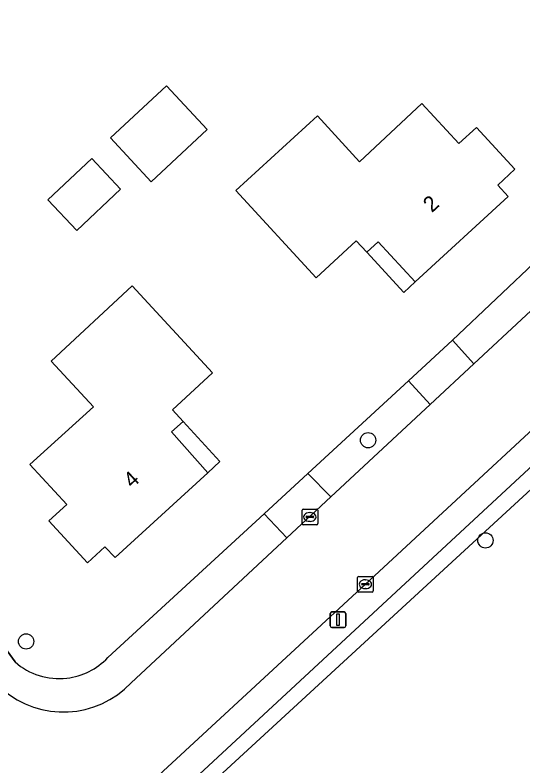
# Model space of a CAD drawing. Extents: x 162661 to 163484, y 380247 to 381230.
# Drawn here: x 163326.21 to 163358.76, y 380933.79 to 380981.87 of the extents above; entities that cross this region are included whole.
import ezdxf

# ---------------------------------------------------------------- set-up
doc = ezdxf.new("R2010")
doc.units = 0
for name, color, linetype in [('IMGEO_Berm_groen', 7, 'Continuous'), ('IMGEO_Boom', 7, 'Continuous'), ('IMGEO_Erf', 7, 'Continuous'), ('IMGEO_Groenvoorziening', 7, 'Continuous'), ('IMGEO_Kolk', 7, 'Continuous'), ('IMGEO_Lichtmast', 7, 'Continuous'), ('IMGEO_Pand', 7, 'Continuous'), ('IMGEO_Pand_nummerreeks', 7, 'Continuous'), ('IMGEO_Pand_overbouw', 7, 'Continuous'), ('IMGEO_Parkeervlak_halfverhard', 7, 'Continuous'), ('IMGEO_Rijbaan_lokaal_gesloten', 7, 'Continuous'), ('IMGEO_Voetpad_open', 7, 'Continuous')]:
    doc.layers.add(name, color=color, linetype=linetype)

msp = doc.modelspace()

# ---------------------------------------------------------------- linework, layer by layer
at = {"layer": 'IMGEO_Berm_groen'}
for points in [[(163326.207, 380940.39), (163325.261, 380941.733), (163311.978, 380956.021)], [(163333.656, 380939.059), (163343.629, 380948.342), (163342.164, 380949.894), (163332.151, 380940.668)]]:
    msp.add_lwpolyline(points, dxfattribs=at)
for centre, radius, start, end in [((163329.039, 380943.604), 4.278, 276.5116, 316.6709), ((163329.034, 380943.61), 4.285, 228.7142, 276.564), ((163329.301, 380943.161), 5.982, 229.0839, 316.7149)]:
    msp.add_arc(centre, radius, start, end, dxfattribs=at)
at = {"layer": 'IMGEO_Boom'}
for centre in [(163348.834, 380954.604), (163356.355, 380948.185), (163326.916, 380941.706)]:
    msp.add_circle(centre, 0.489, dxfattribs=at)
at = {"layer": 'IMGEO_Erf'}
for points in [[(163293.805, 380993.494), (163295.938, 380991.199), (163298.071, 380988.903), (163300.205, 380986.608), (163302.338, 380984.312), (163304.471, 380982.017), (163308.511, 380977.571), (163310.649, 380975.27), (163312.787, 380972.969), (163314.926, 380970.668), (163317.064, 380968.367), (163319.202, 380966.066), (163314.601, 380961.79), (163310.321, 380957.793), (163311.978, 380956.021), (163325.261, 380941.733), (163326.207, 380940.39)], [(163332.151, 380940.668), (163342.164, 380949.894), (163344.981, 380952.467), (163351.42, 380958.415), (163354.236, 380961.019), (163365.428, 380971.625)], [(163404.993, 380933.536), (163403.462, 380935.161), (163390.657, 380948.856), (163386.451, 380953.455), (163376.71, 380963.784), (163373.198, 380964.214), (163372.923, 380964.017), (163339.792, 380933.51), (163323.416, 380918.477), (163320.591, 380915.883), (163309.478, 380905.68), (163306.653, 380903.087), (163296.844, 380894.082)]]:
    msp.add_lwpolyline(points, dxfattribs=at)
for points in [[(163332.317, 380973.987), (163335.909, 380977.334), (163338.528, 380974.523), (163334.936, 380971.177)], [(163340.364, 380970.606), (163345.585, 380975.401), (163348.291, 380972.455), (163352.276, 380976.199), (163354.643, 380973.622), (163355.777, 380974.664), (163358.247, 380971.975), (163357.142, 380970.961), (163357.812, 380970.232), (163351.855, 380964.751), (163349.487, 380967.33), (163348.755, 380966.652), (163348.076, 380967.385), (163345.497, 380965.016)], [(163328.314, 380970.022), (163331.126, 380972.668), (163332.971, 380970.706), (163330.16, 380968.06)], [(163329.52, 380950.478), (163327.148, 380953.052), (163331.23, 380956.744), (163328.515, 380959.683), (163333.723, 380964.494), (163338.874, 380958.919), (163336.297, 380956.547), (163336.973, 380955.812), (163336.236, 380955.134), (163338.555, 380952.513), (163332.63, 380947.079), (163331.958, 380947.767), (163330.855, 380946.75), (163328.385, 380949.431)]]:
    msp.add_lwpolyline(points, close=True, dxfattribs=at)
for centre, radius, start, end in [((163329.039, 380943.604), 4.278, 276.5116, 316.6709), ((163329.034, 380943.61), 4.285, 228.7142, 276.564)]:
    msp.add_arc(centre, radius, start, end, dxfattribs=at)
at = {"layer": 'IMGEO_Groenvoorziening'}
for points in [[(163365.428, 380971.625), (163354.236, 380961.019), (163355.608, 380959.493), (163369.035, 380971.991), (163369.571, 380972.49), (163369.923, 380972.818), (163362.25, 380981.158), (163361.771, 380980.64), (163361.846, 380980.56), (163365.684, 380976.459)], [(163378.593, 380962.733), (163378.306, 380963.06), (163378.763, 380963.459), (163374.975, 380967.47), (163374.087, 380966.646), (163329.24, 380925.031), (163328.116, 380923.988), (163322.814, 380919.162), (163323.416, 380918.477), (163339.792, 380933.51), (163372.923, 380964.017), (163373.198, 380964.214), (163376.71, 380963.784), (163386.451, 380953.455), (163390.657, 380948.856), (163403.462, 380935.161), (163404.993, 380933.536)]]:
    msp.add_lwpolyline(points, dxfattribs=at)
msp.add_lwpolyline([(163346.451, 380950.969), (163352.811, 380956.889), (163351.42, 380958.415), (163344.981, 380952.467)], close=True, dxfattribs=at)
at = {"layer": 'IMGEO_Kolk'}
for p, q in [((163344.603, 380949.26), (163344.603, 380950.112)), ((163344.678, 380950.186), (163345.53, 380950.186)), ((163345.604, 380950.112), (163345.604, 380949.26)), ((163344.862, 380949.68), (163344.862, 380949.692)), ((163345.3, 380949.643), (163344.902, 380949.643)), ((163344.905, 380949.729), (163345.303, 380949.729)), ((163345.091, 380949.966), (163345.116, 380949.966)), ((163345.346, 380949.692), (163345.346, 380949.68)), ((163345.53, 380949.186), (163344.678, 380949.186)), ((163345.114, 380949.406), (163345.089, 380949.406)), ((163348.161, 380944.949), (163348.161, 380945.801)), ((163348.236, 380945.875), (163349.088, 380945.875)), ((163349.162, 380945.801), (163349.162, 380944.949)), ((163348.42, 380945.369), (163348.42, 380945.381)), ((163348.858, 380945.332), (163348.46, 380945.332)), ((163348.463, 380945.418), (163348.861, 380945.418)), ((163348.649, 380945.655), (163348.674, 380945.655)), ((163348.904, 380945.381), (163348.904, 380945.369)), ((163349.088, 380944.875), (163348.236, 380944.875)), ((163348.672, 380945.095), (163348.647, 380945.095))]:
    msp.add_line(p, q, dxfattribs=at)
for points in [[(163344.603, 380949.26), (163344.603, 380950.112)], [(163344.678, 380950.186), (163345.53, 380950.186)], [(163345.604, 380950.112), (163345.604, 380949.26)], [(163345.53, 380949.186), (163344.678, 380949.186)], [(163348.161, 380944.949), (163348.161, 380945.801)], [(163348.236, 380945.875), (163349.088, 380945.875)], [(163349.162, 380945.801), (163349.162, 380944.949)], [(163349.088, 380944.875), (163348.236, 380944.875)]]:
    msp.add_lwpolyline(points, dxfattribs=at)
for centre, radius, start, end in [((163344.68, 380950.11), 0.0765, 91.552, 178.448), ((163344.68, 380950.11), 0.0765, 91.552, 178.448), ((163345.528, 380950.11), 0.0765, 1.552, 88.448), ((163345.528, 380950.11), 0.0765, 1.552, 88.448), ((163344.902, 380949.689), 0.0403, 85.8775, 175.7526), ((163344.899, 380949.679), 0.0366, 178.938, 274.7102), ((163345.303, 380949.686), 0.043, 264.8664, 352.4533), ((163345.307, 380949.691), 0.0386, 1.7309, 96.639), ((163344.68, 380949.262), 0.0765, 181.552, 268.448), ((163344.68, 380949.262), 0.0765, 181.552, 268.448), ((163345.528, 380949.262), 0.0765, 271.552, 358.448), ((163345.528, 380949.262), 0.0765, 271.552, 358.448), ((163348.238, 380945.799), 0.0765, 91.552, 178.448), ((163348.238, 380945.799), 0.0765, 91.552, 178.448), ((163349.086, 380945.799), 0.0765, 1.552, 88.448), ((163349.086, 380945.799), 0.0765, 1.552, 88.448), ((163348.46, 380945.378), 0.0403, 85.8775, 175.7526), ((163348.457, 380945.368), 0.0366, 178.938, 274.7102), ((163348.861, 380945.375), 0.043, 264.8664, 352.4533), ((163348.865, 380945.38), 0.0386, 1.7309, 96.639), ((163348.238, 380944.951), 0.0765, 181.552, 268.448), ((163348.238, 380944.951), 0.0765, 181.552, 268.448), ((163349.086, 380944.951), 0.0765, 271.552, 358.448), ((163349.086, 380944.951), 0.0765, 271.552, 358.448)]:
    msp.add_arc(centre, radius, start, end, dxfattribs=at)
for centre, major_axis, ratio, start_param, end_param in [((163345.09, 380949.686), (-0.387, 0.002), 0.722429, 4.712389, 7.853982), ((163345.115, 380949.686), (-0.39, 0.002), 0.717154, 1.570796, 4.712389), ((163348.648, 380945.375), (-0.387, 0.002), 0.722429, 4.712389, 7.853982), ((163348.673, 380945.375), (-0.39, 0.002), 0.717154, 1.570796, 4.712389)]:
    msp.add_ellipse(centre, major_axis=major_axis, ratio=ratio, start_param=start_param, end_param=end_param, dxfattribs=at)
at = {"layer": 'IMGEO_Lichtmast'}
for p, q in [((163346.408, 380942.7), (163346.408, 380943.5)), ((163346.408, 380943.5), (163346.408, 380942.7)), ((163346.508, 380943.6), (163347.298, 380943.6)), ((163347.298, 380943.6), (163346.508, 380943.6)), ((163347.398, 380943.5), (163347.398, 380942.7)), ((163347.398, 380942.7), (163347.398, 380943.5)), ((163347.298, 380942.6), (163346.508, 380942.6)), ((163346.508, 380942.6), (163347.298, 380942.6))]:
    msp.add_line(p, q, dxfattribs=at)
msp.add_lwpolyline([(163346.828, 380943.475), (163346.978, 380943.475), (163346.978, 380942.725), (163346.828, 380942.725), (163346.828, 380943.475)], dxfattribs=at)
for centre, start, end in [((163346.508, 380943.5), 90, 180), ((163346.508, 380943.5), 90, 180), ((163347.298, 380943.5), 0, 90), ((163347.298, 380943.5), 360, 90), ((163346.508, 380942.7), 180, 270), ((163346.508, 380942.7), 180, 270), ((163347.298, 380942.7), 270, 0), ((163347.298, 380942.7), 270, 0)]:
    msp.add_arc(centre, 0.1, start, end, dxfattribs=at)
at = {"layer": 'IMGEO_Pand'}
for points in [[(163332.317, 380973.987), (163334.936, 380971.177), (163338.528, 380974.523), (163335.909, 380977.334)], [(163348.755, 380966.652), (163349.487, 380967.33), (163351.855, 380964.751), (163357.812, 380970.232), (163357.142, 380970.961), (163358.247, 380971.975), (163355.777, 380974.664), (163354.643, 380973.622), (163352.276, 380976.199), (163348.291, 380972.455), (163345.585, 380975.401), (163340.364, 380970.606), (163345.497, 380965.016), (163348.076, 380967.385)], [(163328.314, 380970.022), (163330.16, 380968.06), (163332.971, 380970.706), (163331.126, 380972.668)], [(163338.555, 380952.513), (163336.236, 380955.134), (163336.973, 380955.812), (163336.297, 380956.547), (163338.874, 380958.919), (163333.723, 380964.494), (163328.515, 380959.683), (163331.23, 380956.744), (163327.148, 380953.052), (163329.52, 380950.478), (163328.385, 380949.431), (163330.855, 380946.75), (163331.958, 380947.767), (163332.63, 380947.079)]]:
    msp.add_lwpolyline(points, close=True, dxfattribs=at)
at = {"layer": 'IMGEO_Pand_overbouw'}
for points in [[(163351.855, 380964.751), (163349.487, 380967.33), (163348.755, 380966.652), (163351.123, 380964.072)], [(163338.555, 380952.513), (163339.344, 380953.233), (163336.973, 380955.812), (163336.236, 380955.134)]]:
    msp.add_lwpolyline(points, close=True, dxfattribs=at)
at = {"layer": 'IMGEO_Parkeervlak_halfverhard'}
msp.add_lwpolyline([(163374.087, 380966.646), (163374.975, 380967.47), (163373.827, 380968.685), (163373.428, 380968.316), (163373.301, 380968.198), (163365.821, 380961.281), (163348.662, 380945.375), (163331.476, 380929.483), (163328.071, 380926.319), (163329.24, 380925.031)], close=True, dxfattribs=at)
at = {"layer": 'IMGEO_Rijbaan_lokaal_gesloten'}
msp.add_lwpolyline([(163318.915, 380917.861), (163321.632, 380920.366), (163326.94, 380925.261), (163328.071, 380926.319), (163331.476, 380929.483), (163348.662, 380945.375), (163365.821, 380961.281), (163373.301, 380968.198), (163373.428, 380968.316), (163369.571, 380972.49), (163369.035, 380971.991), (163355.608, 380959.493), (163352.811, 380956.889), (163346.451, 380950.969), (163343.629, 380948.342), (163333.656, 380939.059)], dxfattribs=at)
msp.add_arc((163329.301, 380943.161), 5.982, 229.0839, 316.7149, dxfattribs=at)
at = {"layer": 'IMGEO_Voetpad_open'}
for points in [[(163355.608, 380959.493), (163354.236, 380961.019), (163351.42, 380958.415), (163352.811, 380956.889)], [(163343.629, 380948.342), (163346.451, 380950.969), (163344.981, 380952.467), (163342.164, 380949.894)]]:
    msp.add_lwpolyline(points, close=True, dxfattribs=at)

# ---------------------------------------------------------------- texts
at = {"layer": 'IMGEO_Pand_nummerreeks'}
for s, rotation, p in [('2', 42.6138, (163352.923, 380969.158)), ('4', 42.5231, (163333.714, 380951.492))]:
    msp.add_text(s, height=1, rotation=rotation, dxfattribs=at).set_placement(p)

doc.saveas('drawing.dxf')
